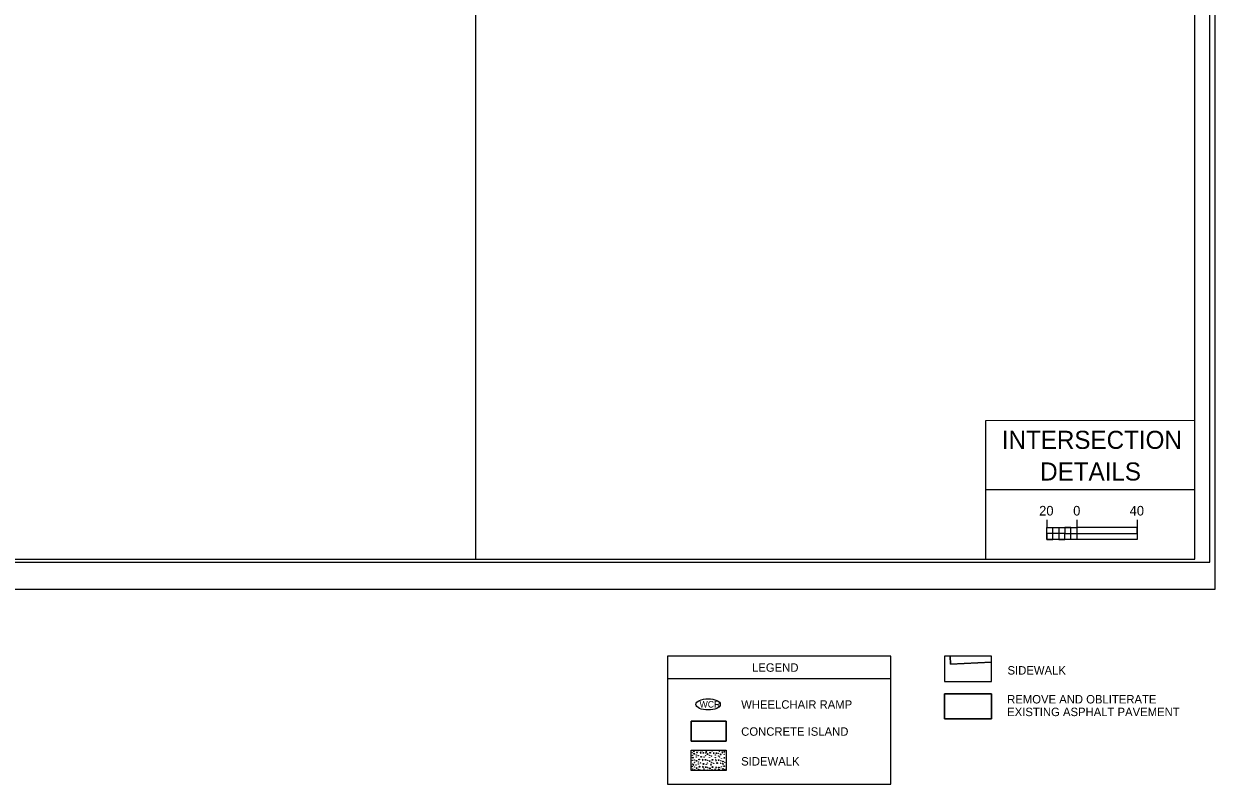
# Model space of a CAD drawing. Extents: x 2431000 to 2534000, y 645879 to 714000.
# Drawn here: x 2467604 to 2468592, y 661112 to 661743 of the extents above; entities that cross this region are included whole.
import ezdxf

# ---------------------------------------------------------------- set-up
doc = ezdxf.new("R2010")
doc.units = 0
for name, color, linetype in [('Default', 7, 'Continuous'), ('KHA_LOGO', 7, 'Continuous'), ('Level 25', 7, 'Continuous'), ('Level 57', 7, 'Continuous'), ('Level 62', 7, 'Continuous'), ('Old_Level_2', 7, 'Continuous'), ('Prop Dimension', 7, 'Continuous'), ('Prop Terminator CELL', 7, 'Continuous'), ('Scratch_Level_1', 7, 'Continuous'), ('Sheet DOT Grid CELL', 7, 'Continuous'), ('Sheet Profile CELL', 7, 'Continuous'), ('Sheet Title Data Points CELL', 7, 'Continuous')]:
    doc.layers.add(name, color=color, linetype=linetype)

msp = doc.modelspace()

# ---------------------------------------------------------------- linework, layer by layer
at = {"layer": 'KHA_LOGO'}
msp.add_line((2468138.13, 661199.49), (2468323.18, 661199.49), dxfattribs=at)
for points in [[(2468575.2, 661413.32), (2468401.64, 661413.27), (2468401.66, 661355.84)], [(2468575.22, 661355.89), (2468401.66, 661355.84), (2468401.67, 661298.4)]]:
    msp.add_lwpolyline(points, dxfattribs=at)
msp.add_lwpolyline([(2468323.18, 661217.81), (2468138.13, 661217.81), (2468138.13, 661111.71), (2468323.18, 661111.71)], close=True, dxfattribs=at)
at = {"layer": 'Level 25'}
msp.add_lwpolyline([(2468367.68, 661186.73), (2468367.68, 661165.96), (2468406.84, 661165.96), (2468406.84, 661186.73), (2468367.68, 661186.73)], dxfattribs=at)
at = {"layer": 'Level 57'}
msp.add_ellipse((2468171.73, 661177.94), major_axis=(10.09, 0), ratio=0.462467, dxfattribs=at)
at = {"layer": 'Level 62'}
msp.add_lwpolyline([(2468367.68, 661217.81), (2468367.68, 661197.04), (2468406.84, 661197.04), (2468406.84, 661217.81), (2468367.68, 661217.81)], dxfattribs=at)
for points in [[(2468367.68, 661186.73), (2468406.84, 661186.73), (2468406.84, 661165.96), (2468367.68, 661165.96)], [(2468157.55, 661164.11), (2468186.74, 661164.11), (2468186.74, 661147.27), (2468157.55, 661147.27)], [(2468157.55, 661139.89), (2468186.74, 661139.89), (2468186.74, 661123.05), (2468157.55, 661123.05)]]:
    msp.add_lwpolyline(points, close=True, dxfattribs=at)
at = {"layer": 'Old_Level_2'}
msp.add_line((2467978.88, 661823.46), (2467978.88, 661298.46), dxfattribs=at)
msp.add_lwpolyline([(2468575.24, 662348.46), (2467075.24, 662348.46), (2467075.24, 661298.46), (2468575.24, 661298.46)], close=True, dxfattribs=at)
at = {"layer": 'Prop Dimension'}
msp.add_lwpolyline([(2466908.74, 661273.46), (2468592.24, 661273.46), (2468592.24, 662373.46), (2466908.74, 662373.46)], close=True, dxfattribs=at)
at = {"layer": 'Prop Terminator CELL'}
msp.add_lwpolyline([(2466921.74, 661295.96), (2468587.74, 661295.96), (2468587.74, 662350.96), (2466921.74, 662350.96)], close=True, dxfattribs=at)
at = {"layer": 'Scratch_Level_1'}
for p, q in [((2468372.82, 661211.21), (2468372.48, 661217.81)), ((2468406.84, 661217.81), (2468372.48, 661217.81)), ((2468372.48, 661217.81), (2468372.82, 661211.21)), ((2468406.84, 661212.91), (2468406.84, 661217.81)), ((2468406.84, 661212.91), (2468372.82, 661211.21)), ((2468372.82, 661211.21), (2468406.84, 661212.91))]:
    msp.add_line(p, q, dxfattribs=at)
msp.add_lwpolyline([(2468372.48, 661217.81), (2468367.68, 661217.81), (2468367.68, 661197.04), (2468406.84, 661197.04), (2468406.84, 661212.91)], dxfattribs=at)
at = {"layer": 'Sheet Profile CELL'}
for p, q in [((2468452.56, 661330.93), (2468452.56, 661324.68)), ((2468477.56, 661330.93), (2468477.56, 661324.68))]:
    msp.add_line(p, q, dxfattribs=at)
msp.add_lwpolyline([(2468527.56, 661330.93), (2468527.56, 661314.68), (2468452.56, 661314.68), (2468452.56, 661324.68), (2468477.56, 661324.68)], dxfattribs=at)
for points in [[(2468462.56, 661319.68), (2468457.56, 661319.68), (2468457.56, 661324.68), (2468462.56, 661324.68)], [(2468472.56, 661324.68), (2468467.56, 661324.68), (2468467.56, 661319.68), (2468472.56, 661319.68)], [(2468527.56, 661324.68), (2468477.56, 661324.68), (2468477.56, 661319.68), (2468527.56, 661319.68)], [(2468457.56, 661319.68), (2468452.56, 661319.68), (2468452.56, 661314.68), (2468457.56, 661314.68)], [(2468467.56, 661319.68), (2468462.56, 661319.68), (2468462.56, 661314.68), (2468467.56, 661314.68)], [(2468477.56, 661314.68), (2468472.56, 661314.68), (2468472.56, 661319.68), (2468477.56, 661319.68)]]:
    msp.add_lwpolyline(points, close=True, dxfattribs=at)
at = {"layer": 'Sheet Title Data Points CELL'}
msp.add_lwpolyline([(2468157.55, 661164.11), (2468157.55, 661147.27), (2468186.74, 661147.27), (2468186.74, 661164.11), (2468157.55, 661164.11)], dxfattribs=at)
for points in [[(2468165.89, 661137.65), (2468165.14, 661138.25), (2468165.32, 661137.22)], [(2468170.54, 661138.53), (2468169.79, 661139.13), (2468169.97, 661138.1)], [(2468176.82, 661137.36), (2468176.07, 661137.96), (2468176.25, 661136.93)], [(2468183.97, 661137.93), (2468183.22, 661138.53), (2468183.4, 661137.5)], [(2468159.99, 661127.71), (2468159.25, 661128.31), (2468159.42, 661127.28)], [(2468167.69, 661131.76), (2468166.95, 661132.36), (2468167.12, 661131.33)], [(2468167.85, 661125.74), (2468167.11, 661126.34), (2468167.28, 661125.31)], [(2468174.59, 661127.87), (2468173.84, 661128.47), (2468174.02, 661127.44)], [(2468178.62, 661131.47), (2468177.88, 661132.07), (2468178.05, 661131.04)], [(2468178.79, 661125.46), (2468178.04, 661126.06), (2468178.21, 661125.03)], [(2468184.41, 661128.43), (2468183.66, 661129.03), (2468183.84, 661128)], [(2468177.95, 661123.94), (2468177.21, 661124.54), (2468177.38, 661123.51)]]:
    msp.add_lwpolyline(points, close=True, dxfattribs=at)
for centre, radius in [((2468158.57, 661137.75), 0.131), ((2468158.57, 661135.58), 0.131), ((2468159.78, 661139.06), 0.356), ((2468160.25, 661136.97), 0.356), ((2468161.98, 661135.96), 0.131), ((2468162.5, 661138.09), 0.356), ((2468163.73, 661139.5), 0.131), ((2468166.7, 661139.34), 0.131), ((2468167.75, 661137.77), 0.356), ((2468169.5, 661137.46), 0.131), ((2468171.18, 661136.69), 0.356), ((2468172.91, 661135.67), 0.131), ((2468173.44, 661137.8), 0.356), ((2468174.96, 661139.34), 0.131), ((2468177.76, 661135.98), 0.131), ((2468178.69, 661137.48), 0.356), ((2468180.44, 661137.18), 0.131), ((2468181.25, 661139.06), 0.131), ((2468182.12, 661136.4), 0.356), ((2468185.19, 661138.61), 0.356), ((2468185.06, 661136.42), 0.131), ((2468158.21, 661126.43), 0.356), ((2468158.68, 661131.49), 0.131), ((2468158.68, 661128.56), 0.131), ((2468159.1, 661133.72), 0.356), ((2468160.37, 661131.86), 0.131), ((2468160.38, 661129.69), 0.131), ((2468160.53, 661125.84), 0.131), ((2468161.61, 661127.56), 0.131), ((2468162.05, 661131.08), 0.356), ((2468161.88, 661134.32), 0.131), ((2468163.6, 661135.28), 0.131), ((2468163.68, 661128.43), 0.131), ((2468163.78, 661130.07), 0.131), ((2468164.31, 661132.19), 0.356), ((2468164.47, 661126.18), 0.356), ((2468165.41, 661129.38), 0.131), ((2468165.98, 661134.42), 0.356), ((2468167.79, 661128.53), 0.356), ((2468168.42, 661134.15), 0.131), ((2468169.56, 661131.88), 0.356), ((2468169.72, 661125.87), 0.356), ((2468169.51, 661135.3), 0.131), ((2468170.23, 661128.26), 0.131), ((2468171.31, 661131.57), 0.131), ((2468171.31, 661129.4), 0.131), ((2468171.47, 661125.56), 0.131), ((2468172.99, 661130.79), 0.356), ((2468172.87, 661134.05), 0.131), ((2468174.54, 661134.99), 0.131), ((2468174.72, 661129.78), 0.131), ((2468175.24, 661131.91), 0.356), ((2468175.4, 661125.89), 0.356), ((2468176.34, 661129.09), 0.131), ((2468177.76, 661133.73), 0.131), ((2468179.14, 661129.23), 0.356), ((2468180.49, 661131.59), 0.356), ((2468180.65, 661125.58), 0.356), ((2468180.44, 661135.01), 0.131), ((2468181.13, 661134.17), 0.131), ((2468182.24, 661131.28), 0.131), ((2468182.24, 661129.11), 0.131), ((2468182.82, 661132.77), 0.131), ((2468182.82, 661126.44), 0.131), ((2468183.92, 661130.51), 0.356), ((2468185.03, 661126.71), 0.356), ((2468185.15, 661133.6), 0.356), ((2468185.46, 661129.96), 0.131), ((2468158.96, 661124.35), 0.131), ((2468160.54, 661123.68), 0.131), ((2468162.21, 661125.07), 0.356), ((2468163.94, 661124.06), 0.131), ((2468165.57, 661123.37), 0.131), ((2468168.27, 661124.22), 0.131), ((2468171.47, 661123.39), 0.131), ((2468173.15, 661124.78), 0.356), ((2468174.88, 661123.77), 0.131), ((2468180.54, 661123.9), 0.356), ((2468182.4, 661125.27), 0.131), ((2468184.08, 661124.49), 0.356), ((2468185.62, 661124.07), 0.131)]:
    msp.add_circle(centre, radius, dxfattribs=at)

# ---------------------------------------------------------------- texts
at = {"layer": 'Default'}
for s, p in [('LEGEND', (2468208.16, 661204.98)), ('REMOVE AND OBLITERATE', (2468419.73, 661178.68)), ('EXISTING ASPHALT PAVEMENT', (2468419.73, 661168.18))]:
    msp.add_text(s, height=7, dxfattribs=at).set_placement(p)
for s, rotation, p in [('SIDEWALK', 0.01753, (2468420.04, 661202.64)), ('WHEELCHAIR RAMP', 359.99994, (2468199.14, 661174.33)), ('CONCRETE ISLAND', 359.99994, (2468199.14, 661151.88)), ('SIDEWALK', 359.99994, (2468199.14, 661127.19))]:
    msp.add_text(s, height=7, rotation=rotation, dxfattribs=at).set_placement(p)
at = {"layer": 'Level 57'}
msp.add_text('WCR', height=5.4, dxfattribs=at).set_placement((2468164.6, 661175.28))
at = {"layer": 'Sheet DOT Grid CELL'}
for s, p in [('INTERSECTION', (2468415.28, 661389.91)), ('DETAILS', (2468447.11, 661363.66))]:
    msp.add_text(s, height=15, rotation=360, dxfattribs=at).set_placement(p)
at = {"layer": 'Sheet Profile CELL'}
for s, p in [('20', (2468446.28, 661334.6)), ('0', (2468474.48, 661334.6)), ('40', (2468521.32, 661334.6))]:
    msp.add_text(s, height=8, dxfattribs=at).set_placement(p)

doc.saveas('drawing.dxf')
